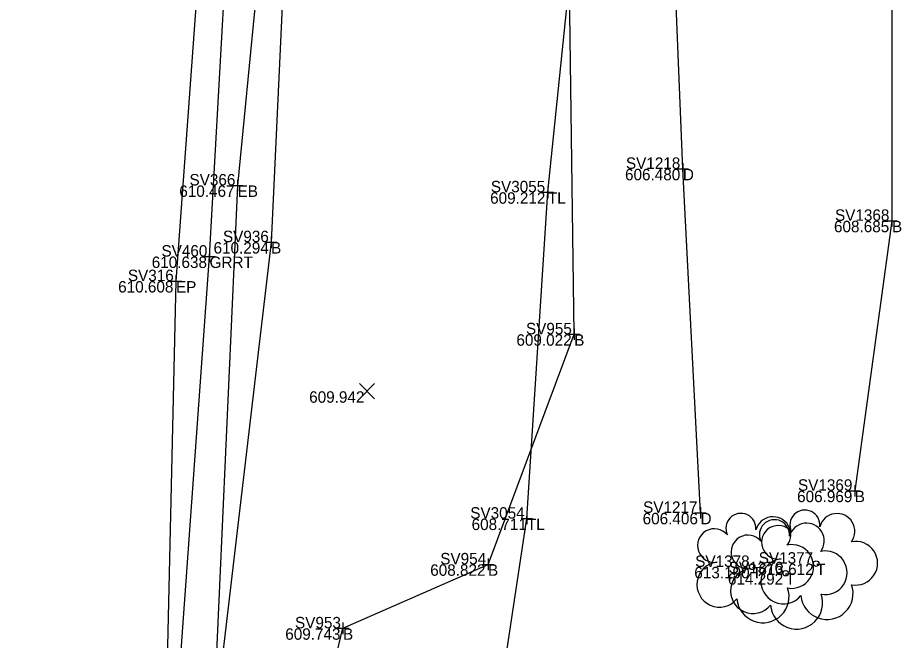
# Model space of a CAD drawing. Extents: x -2 to 1979875, y -2 to 232027.
# Drawn here: x 1978775.86 to 1978814.52, y 231206.93 to 231234.17 of the extents above; entities that cross this region are included whole.
import ezdxf

# ---------------------------------------------------------------- set-up
doc = ezdxf.new("R2010")
doc.units = 0
for name, color, linetype in [('_CIVIL_CONSTRUCTION', 7, 'Continuous'), ('DR_X_Ditch', 7, 'Continuous'), ('GE_P_Alignment', 7, 'Continuous'), ('GE_P_Alignment_1000_Curve_Data', 7, 'Continuous'), ('GE_P_Alignment_1000_Stations', 7, 'Continuous'), ('GE_X_Alignment', 7, 'Continuous'), ('GE_X_Alignment_1000_Stations', 7, 'Continuous'), ('GE_X_Alignment_100_Curve_Data', 7, 'Continuous'), ('GE_X_Alignment_100_Stations', 7, 'Continuous'), ('SC_Scratch1', 7, 'Continuous'), ('SV_X_Random_Point', 7, 'Continuous'), ('VG_X_Cells', 7, 'Continuous')]:
    doc.layers.add(name, color=color, linetype=linetype)

msp = doc.modelspace()

# ---------------------------------------------------------------- linework, layer by layer
at = {"layer": 'DR_X_Ditch'}
msp.add_lwpolyline([(1978805.733, 231212.508), (1978804.96, 231227.558), (1978804.457, 231239.752), (1978804.385, 231249.881), (1978804.498, 231253.577)], dxfattribs=at)
at = {"layer": 'GE_P_Alignment'}
for points in [[(1978812.863, 231249.753), (1978814.099, 231236.437), (1978814.107, 231225.285), (1978812.479, 231213.477)], [(1978788.119, 231249.408), (1978786.943, 231224.352), (1978784.459, 231203.181), (1978783.148, 231179.495), (1978781.259, 231158.933), (1978779.831, 231135.814), (1978779.399, 231114.976), (1978780.51, 231101.208), (1978780.469, 231098.542), (1978778.925, 231080.086), (1978777.811, 231054.63), (1978776.389, 231030.876)], [(1978782.883, 231095.387), (1978784.018, 231105.569), (1978783.215, 231126.435), (1978783.474, 231146.96), (1978785.203, 231170.705), (1978786.559, 231192.76), (1978790.09, 231207.457), (1978796.435, 231210.256), (1978800.205, 231220.321), (1978799.997, 231235.458), (1978797.94, 231243.541), (1978796.315, 231248.532)]]:
    msp.add_lwpolyline(points, dxfattribs=at)
at = {"layer": 'GE_P_Alignment_1000_Curve_Data'}
msp.add_lwpolyline([(1978791.661, 231060.333), (1978792.296, 231074.691), (1978791.754, 231088.963), (1978792.43, 231104.517), (1978792.032, 231117.838), (1978792.133, 231132.395), (1978792.905, 231147.152), (1978794.82, 231159.979), (1978795.624, 231173.18), (1978796.399, 231188.281), (1978796.48, 231201.342), (1978798.136, 231212.257), (1978799.055, 231226.533), (1978800.349, 231239.171), (1978800.253, 231250.204), (1978805.284, 231291.391)], dxfattribs=at)
at = {"layer": 'GE_P_Alignment_1000_Stations'}
msp.add_lwpolyline([(1978779.18, 231099.769), (1978777.975, 231123.065), (1978779.192, 231147.605), (1978781.012, 231172.97), (1978782.386, 231197.771), (1978784.253, 231223.721), (1978785.562, 231247.078)], dxfattribs=at)
at = {"layer": 'GE_X_Alignment_1000_Stations'}
msp.add_lwpolyline([(1978785.568, 231251.827), (1978784.19, 231242.096), (1978782.784, 231222.648), (1978782.32, 231202.663), (1978780.702, 231177.057), (1978778.946, 231150.803), (1978777.805, 231126.797), (1978776.986, 231106.931), (1978775.705, 231085.257), (1978774.572, 231063.753), (1978773.517, 231041.76), (1978772.029, 231016.51), (1978770.7, 230994.507), (1978769.257, 230972.092), (1978767.73, 230948.595), (1978766.192, 230924.232), (1978764.603, 230899.039), (1978762.827, 230873.547), (1978761.273, 230848.668), (1978759.848, 230822.744), (1978759.345, 230799.915), (1978760.114, 230777.862), (1978762.938, 230755.551), (1978769.839, 230729.514)], dxfattribs=at)
at = {"layer": 'GE_X_Alignment_100_Curve_Data'}
for p, q in [((1978804.96, 231227.808), (1978804.96, 231227.308)), ((1978804.71, 231227.558), (1978805.21, 231227.558)), ((1978804.96, 231227.558), (1978804.96, 231227.558)), ((1978785.48, 231227.083), (1978785.48, 231226.583)), ((1978785.23, 231226.833), (1978785.73, 231226.833)), ((1978785.48, 231226.833), (1978785.48, 231226.833)), ((1978799.055, 231226.783), (1978799.055, 231226.283)), ((1978798.805, 231226.533), (1978799.305, 231226.533)), ((1978799.055, 231226.533), (1978799.055, 231226.533)), ((1978814.107, 231225.535), (1978814.107, 231225.035)), ((1978813.857, 231225.285), (1978814.357, 231225.285)), ((1978814.107, 231225.285), (1978814.107, 231225.285)), ((1978786.693, 231224.352), (1978787.193, 231224.352)), ((1978786.943, 231224.602), (1978786.943, 231224.102)), ((1978786.943, 231224.352), (1978786.943, 231224.352)), ((1978784.253, 231223.971), (1978784.253, 231223.471)), ((1978784.003, 231223.721), (1978784.503, 231223.721)), ((1978784.253, 231223.721), (1978784.253, 231223.721)), ((1978782.784, 231222.898), (1978782.784, 231222.398)), ((1978782.534, 231222.648), (1978783.034, 231222.648)), ((1978782.784, 231222.648), (1978782.784, 231222.648)), ((1978800.205, 231220.571), (1978800.205, 231220.071)), ((1978799.955, 231220.321), (1978800.455, 231220.321)), ((1978800.205, 231220.321), (1978800.205, 231220.321)), ((1978812.229, 231213.477), (1978812.729, 231213.477)), ((1978812.479, 231213.727), (1978812.479, 231213.227)), ((1978812.479, 231213.477), (1978812.479, 231213.477)), ((1978805.733, 231212.758), (1978805.733, 231212.258)), ((1978797.886, 231212.257), (1978798.386, 231212.257)), ((1978798.136, 231212.507), (1978798.136, 231212.007)), ((1978798.136, 231212.257), (1978798.136, 231212.257)), ((1978805.483, 231212.508), (1978805.983, 231212.508)), ((1978805.733, 231212.508), (1978805.733, 231212.508)), ((1978796.435, 231210.506), (1978796.435, 231210.006)), ((1978796.185, 231210.256), (1978796.685, 231210.256)), ((1978796.435, 231210.256), (1978796.435, 231210.256)), ((1978790.09, 231207.707), (1978790.09, 231207.207)), ((1978789.84, 231207.457), (1978790.34, 231207.457)), ((1978790.09, 231207.457), (1978790.09, 231207.457))]:
    msp.add_line(p, q, dxfattribs=at)
at = {"layer": 'SC_Scratch1'}
msp.add_lwpolyline([(1978787.694, 231249.601), (1978785.48, 231226.833), (1978784.558, 231206.407), (1978783.016, 231187.193), (1978782.112, 231167.584), (1978780.51, 231145.937), (1978779.287, 231125.907), (1978778.425, 231108.773), (1978777.775, 231087.524), (1978776.748, 231064.782), (1978775.35, 231040.582), (1978774.462, 231016.281), (1978772.549, 230990.683), (1978771.051, 230965.635), (1978769.086, 230942.407), (1978767.324, 230917.989), (1978765.95, 230893.701), (1978764.896, 230870.53), (1978763.088, 230848.633), (1978761.583, 230826.273), (1978760.498, 230804.271), (1978761.5, 230780.247), (1978763.845, 230755.469), (1978770.352, 230731.454)], dxfattribs=at)
at = {"layer": 'SV_X_Random_Point'}
for p, q in [((1978790.806, 231217.493), (1978791.472, 231218.161)), ((1978790.806, 231218.161), (1978791.472, 231217.493))]:
    msp.add_line(p, q, dxfattribs=at)
at = {"layer": 'VG_X_Cells'}
for centre in [(1978810.792, 231210.289), (1978807.991, 231210.145), (1978809.459, 231209.868)]:
    msp.add_circle(centre, 0.12, dxfattribs=at)
for centre, radius, start, end in [((1978807.499, 231211.829), 0.658, 354.0047, 205.9741), ((1978808.904, 231211.56), 0.776, 323.83, 165.0376), ((1978810.3, 231211.973), 0.658, 354.0047, 205.9741), ((1978811.705, 231211.704), 0.776, 323.83, 165.0376), ((1978808.967, 231211.552), 0.658, 354.0047, 205.9741), ((1978809.137, 231211.221), 0.735, 39.0625, 279.5412), ((1978810.372, 231211.283), 0.776, 323.83, 165.0376), ((1978806.336, 231211.077), 0.735, 39.0625, 279.5412), ((1978807.804, 231210.8), 0.735, 39.0625, 279.5412), ((1978809.721, 231210.163), 0.957, 259.1453, 101.4596), ((1978812.522, 231210.307), 0.957, 259.1453, 101.4596), ((1978811.189, 231209.886), 0.957, 259.1453, 101.4596), ((1978806.564, 231209.371), 0.987, 96.1722, 320.5737), ((1978809.365, 231209.515), 0.987, 96.1722, 320.5737), ((1978808.032, 231209.094), 0.987, 96.1722, 320.5737), ((1978808.464, 231208.842), 1.142, 184.9476, 19.4572), ((1978811.265, 231208.986), 1.142, 184.9476, 19.4572), ((1978809.932, 231208.565), 1.142, 184.9476, 19.4572)]:
    msp.add_arc(centre, radius, start, end, dxfattribs=at)

# ---------------------------------------------------------------- texts
at = {"layer": '_CIVIL_CONSTRUCTION'}
for s, p in [('606.480', (1978802.43, 231227.058)), ('610.467', (1978782.929, 231226.333)), ('609.212', (1978796.527, 231226.033)), ('608.685', (1978811.572, 231224.785)), ('610.294', (1978784.427, 231223.852)), ('610.638', (1978781.723, 231223.221)), ('610.608', (1978780.254, 231222.148)), ('609.022', (1978797.677, 231219.821)), ('609.942', (1978788.611, 231217.327)), ('606.969', (1978809.958, 231212.977)), ('608.711', (1978795.718, 231211.757)), ('606.406', (1978803.201, 231212.008)), ('608.822', (1978793.907, 231209.756)), ('613.190', (1978805.461, 231209.645)), ('613.612', (1978808.264, 231209.789)), ('614.292', (1978806.931, 231209.368)), ('609.743', (1978787.565, 231206.957))]:
    msp.add_text(s, height=0.5, dxfattribs=at).set_placement(p)
at = {"layer": 'GE_X_Alignment'}
for s, p in [('SV1218', (1978802.469, 231227.558)), ('SV366', (1978783.375, 231226.833)), ('SV3055', (1978796.558, 231226.533)), ('SV1368', (1978811.616, 231225.285)), ('SV936', (1978784.838, 231224.352)), ('SV460', (1978782.149, 231223.721)), ('SV316', (1978780.679, 231222.648)), ('SV955', (1978798.096, 231220.321)), ('SV1369', (1978809.997, 231213.477)), ('SV3054', (1978795.659, 231212.257)), ('SV1217', (1978803.22, 231212.508)), ('SV954', (1978794.346, 231210.256)), ('SV1377', (1978808.279, 231210.289)), ('SV1378', (1978805.5, 231210.145)), ('SV1376', (1978806.965, 231209.868)), ('SV953', (1978787.992, 231207.457))]:
    msp.add_text(s, height=0.5, dxfattribs=at).set_placement(p)
at = {"layer": 'GE_X_Alignment_100_Stations'}
for s, p in [('D', (1978804.96, 231227.058)), ('EB', (1978785.48, 231226.333)), ('TL', (1978799.055, 231226.033)), ('B', (1978814.107, 231224.785)), ('B', (1978786.943, 231223.852)), ('GRRT', (1978784.253, 231223.221)), ('EP', (1978782.784, 231222.148)), ('B', (1978800.205, 231219.821)), ('B', (1978812.479, 231212.977)), ('TL', (1978798.136, 231211.757)), ('D', (1978805.733, 231212.008)), ('B', (1978796.435, 231209.756)), ('T', (1978807.991, 231209.645)), ('T', (1978810.792, 231209.789)), ('T', (1978809.459, 231209.368)), ('B', (1978790.09, 231206.957))]:
    msp.add_text(s, height=0.5, dxfattribs=at).set_placement(p)

doc.saveas('drawing.dxf')
